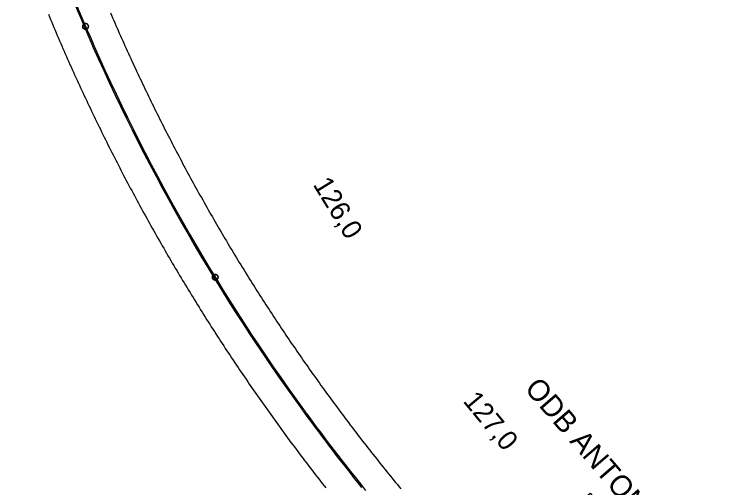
# Model space of a CAD drawing. Extents: x -670810 to -649614, y -1131928 to -1115069.
# Drawn here: x -670388 to -667816, y -1121929 to -1120256 of the extents above; entities that cross this region are included whole.
import ezdxf

# ---------------------------------------------------------------- set-up
doc = ezdxf.new("R2010")
doc.units = 0
for name, color, linetype in [('519 Var SK-4 Praporky stanic', 7, 'Continuous'), ('hranice_VRT_ZUR_Vysocina', 7, 'Continuous'), ('Situace - Osa koleje 2D', 7, 'Continuous'), ('Situace - Osa koleje tunel 2D', 7, 'Continuous'), ('Staničení - hlavní staničení + kolečka 1k', 7, 'Continuous')]:
    doc.layers.add(name, color=color, linetype=linetype)

# ---------------------------------------------------------------- blocks, each defined once
blk = doc.blocks.new('Sit10Kruh_102')
at = {"layer": 'Staničení - hlavní staničení + kolečka 1k'}
blk.add_lwpolyline([(10, 0), (10, 0.6), (9.9, 1.3), (9.8, 1.9), (9.7, 2.5), (9.5, 3.1), (9.3, 3.7), (9, 4.3), (8.8, 4.8), (8.4, 5.4), (8.1, 5.9), (7.7, 6.4), (7.3, 6.8), (6.8, 7.3), (6.4, 7.7), (5.9, 8.1), (5.4, 8.4), (4.8, 8.8), (4.3, 9), (3.7, 9.3), (3.1, 9.5), (2.5, 9.7), (1.9, 9.8), (1.3, 9.9), (0.6, 10), (0, 10), (-0.6, 10), (-1.3, 9.9), (-1.9, 9.8), (-2.5, 9.7), (-3.1, 9.5), (-3.7, 9.3), (-4.3, 9), (-4.8, 8.8), (-5.4, 8.4), (-5.9, 8.1), (-6.4, 7.7), (-6.8, 7.3), (-7.3, 6.8), (-7.7, 6.4), (-8.1, 5.9), (-8.4, 5.4), (-8.8, 4.8), (-9, 4.3), (-9.3, 3.7), (-9.5, 3.1), (-9.7, 2.5), (-9.8, 1.9), (-9.9, 1.3), (-10, 0.6), (-10, 0), (-10, -0.6), (-9.9, -1.3), (-9.8, -1.9), (-9.7, -2.5), (-9.5, -3.1), (-9.3, -3.7), (-9, -4.3), (-8.8, -4.8), (-8.4, -5.4), (-8.1, -5.9), (-7.7, -6.4), (-7.3, -6.8), (-6.8, -7.3), (-6.4, -7.7), (-5.9, -8.1), (-5.4, -8.4), (-4.8, -8.8), (-4.3, -9), (-3.7, -9.3), (-3.1, -9.5), (-2.5, -9.7), (-1.9, -9.8), (-1.3, -9.9), (-0.6, -10), (0, -10), (0.6, -10), (1.3, -9.9), (1.9, -9.8), (2.5, -9.7), (3.1, -9.5), (3.7, -9.3), (4.3, -9), (4.8, -8.8), (5.4, -8.4), (5.9, -8.1), (6.4, -7.7), (6.8, -7.3), (7.3, -6.8), (7.7, -6.4), (8.1, -5.9), (8.4, -5.4), (8.8, -4.8), (9, -4.3), (9.3, -3.7), (9.5, -3.1), (9.7, -2.5), (9.8, -1.9), (9.9, -1.3)], close=True, dxfattribs=at)
blk.add_circle((0, 0), 10, dxfattribs=at)
blk = doc.blocks.new('Sit10Kruh_103')
at = {"layer": 'Staničení - hlavní staničení + kolečka 1k'}
blk.add_lwpolyline([(10, 0), (10, 0.6), (9.9, 1.3), (9.8, 1.9), (9.7, 2.5), (9.5, 3.1), (9.3, 3.7), (9, 4.3), (8.8, 4.8), (8.4, 5.4), (8.1, 5.9), (7.7, 6.4), (7.3, 6.8), (6.8, 7.3), (6.4, 7.7), (5.9, 8.1), (5.4, 8.4), (4.8, 8.8), (4.3, 9), (3.7, 9.3), (3.1, 9.5), (2.5, 9.7), (1.9, 9.8), (1.3, 9.9), (0.6, 10), (0, 10), (-0.6, 10), (-1.3, 9.9), (-1.9, 9.8), (-2.5, 9.7), (-3.1, 9.5), (-3.7, 9.3), (-4.3, 9), (-4.8, 8.8), (-5.4, 8.4), (-5.9, 8.1), (-6.4, 7.7), (-6.8, 7.3), (-7.3, 6.8), (-7.7, 6.4), (-8.1, 5.9), (-8.4, 5.4), (-8.8, 4.8), (-9, 4.3), (-9.3, 3.7), (-9.5, 3.1), (-9.7, 2.5), (-9.8, 1.9), (-9.9, 1.3), (-10, 0.6), (-10, 0), (-10, -0.6), (-9.9, -1.3), (-9.8, -1.9), (-9.7, -2.5), (-9.5, -3.1), (-9.3, -3.7), (-9, -4.3), (-8.8, -4.8), (-8.4, -5.4), (-8.1, -5.9), (-7.7, -6.4), (-7.3, -6.8), (-6.8, -7.3), (-6.4, -7.7), (-5.9, -8.1), (-5.4, -8.4), (-4.8, -8.8), (-4.3, -9), (-3.7, -9.3), (-3.1, -9.5), (-2.5, -9.7), (-1.9, -9.8), (-1.3, -9.9), (-0.6, -10), (0, -10), (0.6, -10), (1.3, -9.9), (1.9, -9.8), (2.5, -9.7), (3.1, -9.5), (3.7, -9.3), (4.3, -9), (4.8, -8.8), (5.4, -8.4), (5.9, -8.1), (6.4, -7.7), (6.8, -7.3), (7.3, -6.8), (7.7, -6.4), (8.1, -5.9), (8.4, -5.4), (8.8, -4.8), (9, -4.3), (9.3, -3.7), (9.5, -3.1), (9.7, -2.5), (9.8, -1.9), (9.9, -1.3)], close=True, dxfattribs=at)
blk.add_circle((0, 0), 10, dxfattribs=at)
blk = doc.blocks.new('_U497')
at = {"layer": '519 Var SK-4 Praporky stanic'}
blk.add_line((-45.8, -299.9), (-45.8, 299.9), dxfattribs=at)
blk.add_lwpolyline([(-45.8, 299.9), (104.2, 299.9), (54.2, 249.9), (104.2, 199.9), (-45.8, 199.9)], close=True, dxfattribs=at)
for s, p in [('km 127,451', (-97.4, -108.5)), ('= km 0,000', (-59.2, -104))]:
    blk.add_text(s, height=30, rotation=90, dxfattribs=at).set_placement(p)
blk = doc.blocks.new('_U496')
at = {"layer": '519 Var SK-4 Praporky stanic'}
blk.add_blockref('_U497', (45.8, -87.5), dxfattribs=at)
blk.add_text('ODB ANTONÍNŮV DŮL', height=75, dxfattribs=at).set_placement((-432.7, 274.9))

msp = doc.modelspace()

# ---------------------------------------------------------------- linework, layer by layer
at = {"layer": 'hranice_VRT_ZUR_Vysocina'}
for points in [[(-670047.9, -1120249.3), (-670044, -1120258.3), (-670040.1, -1120267.4), (-670036.2, -1120276.4), (-670032.3, -1120285.5), (-670028.4, -1120294.5), (-670024.4, -1120303.5), (-670020.4, -1120312.5), (-670016.5, -1120321.6), (-670012.5, -1120330.6), (-670008.5, -1120339.6), (-670004.4, -1120348.6), (-670000.4, -1120357.6), (-669996.4, -1120366.6), (-669992.3, -1120375.6), (-669988.3, -1120384.5), (-669984.2, -1120393.5), (-669980.1, -1120402.5), (-669976, -1120411.4), (-669971.9, -1120420.4), (-669967.7, -1120429.3), (-669963.6, -1120438.3), (-669959.4, -1120447.2), (-669955.2, -1120456.2), (-669951.1, -1120465.1), (-669946.9, -1120474), (-669942.7, -1120482.9), (-669938.4, -1120491.8), (-669934.2, -1120500.7), (-669930, -1120509.6), (-669925.7, -1120518.5), (-669921.4, -1120527.4), (-669917.1, -1120536.3), (-669912.8, -1120545.1), (-669908.5, -1120554), (-669904.2, -1120562.9), (-669899.9, -1120571.7), (-669895.5, -1120580.6), (-669891.2, -1120589.4), (-669886.8, -1120598.2), (-669882.4, -1120607.1), (-669878, -1120615.9), (-669873.6, -1120624.7), (-669869.2, -1120633.5), (-669864.7, -1120642.3), (-669860.3, -1120651.1), (-669855.8, -1120659.9), (-669851.4, -1120668.7), (-669846.9, -1120677.5), (-669842.4, -1120686.2), (-669837.9, -1120695), (-669833.3, -1120703.7), (-669828.8, -1120712.5), (-669824.2, -1120721.2), (-669819.7, -1120730), (-669815.1, -1120738.7), (-669810.5, -1120747.4), (-669805.9, -1120756.2), (-669801.3, -1120764.9), (-669796.7, -1120773.6), (-669792.1, -1120782.3), (-669787.4, -1120791), (-669782.7, -1120799.6), (-669778.1, -1120808.3), (-669773.4, -1120817), (-669768.7, -1120825.7), (-669764, -1120834.3), (-669759.3, -1120843), (-669754.5, -1120851.6), (-669749.8, -1120860.3), (-669745, -1120868.9), (-669740.2, -1120877.5), (-669735.4, -1120886.1), (-669730.7, -1120894.7), (-669725.8, -1120903.3), (-669721, -1120911.9), (-669716.2, -1120920.5), (-669711.3, -1120929.1), (-669706.5, -1120937.7), (-669701.6, -1120946.3), (-669696.7, -1120954.8), (-669691.8, -1120963.4), (-669686.9, -1120971.9), (-669682, -1120980.5), (-669677.1, -1120989), (-669672.1, -1120997.5), (-669667.2, -1121006.1), (-669662.2, -1121014.6), (-669657.2, -1121023.1), (-669652.2, -1121031.6), (-669647.2, -1121040.1), (-669642.2, -1121048.6), (-669637.2, -1121057), (-669632.1, -1121065.5), (-669627.1, -1121074), (-669622, -1121082.4), (-669616.9, -1121090.9), (-669611.9, -1121099.3), (-669606.8, -1121107.7), (-669601.6, -1121116.2), (-669596.5, -1121124.6), (-669591.4, -1121133), (-669586.2, -1121141.4), (-669581.1, -1121149.8), (-669575.9, -1121158.2), (-669570.7, -1121166.6), (-669565.5, -1121175), (-669560.3, -1121183.3), (-669555.1, -1121191.7), (-669549.8, -1121200), (-669544.6, -1121208.4), (-669539.3, -1121216.7), (-669534.1, -1121225.1), (-669528.8, -1121233.4), (-669523.5, -1121241.7), (-669518.2, -1121250), (-669512.9, -1121258.3), (-669507.5, -1121266.6), (-669502.2, -1121274.9), (-669496.9, -1121283.2), (-669491.5, -1121291.4), (-669486.1, -1121299.7), (-669480.7, -1121307.9), (-669475.3, -1121316.2), (-669469.9, -1121324.4), (-669464.5, -1121332.7), (-669459.1, -1121340.9), (-669453.6, -1121349.1), (-669448.2, -1121357.3), (-669442.7, -1121365.5), (-669437.2, -1121373.7), (-669431.7, -1121381.9), (-669426.2, -1121390.1), (-669420.7, -1121398.2), (-669415.2, -1121406.4), (-669409.6, -1121414.5), (-669404.1, -1121422.7), (-669398.5, -1121430.8), (-669392.9, -1121439), (-669387.3, -1121447.1), (-669381.7, -1121455.2), (-669376.1, -1121463.3), (-669370.5, -1121471.4), (-669364.9, -1121479.5), (-669359.2, -1121487.6), (-669353.6, -1121495.6), (-669347.9, -1121503.7), (-669342.2, -1121511.8), (-669336.5, -1121519.8), (-669330.8, -1121527.8), (-669325.1, -1121535.9), (-669319.4, -1121543.9), (-669313.7, -1121551.9), (-669307.9, -1121559.9), (-669302.2, -1121567.9), (-669296.4, -1121575.9), (-669290.6, -1121583.9), (-669284.8, -1121591.9), (-669279, -1121599.8), (-669273.2, -1121607.8), (-669267.4, -1121615.7), (-669261.5, -1121623.7), (-669255.7, -1121631.6), (-669249.8, -1121639.5), (-669243.9, -1121647.5), (-669238.1, -1121655.4), (-669232.2, -1121663.3), (-669226.3, -1121671.2), (-669220.3, -1121679), (-669214.4, -1121686.9), (-669208.5, -1121694.8), (-669202.5, -1121702.7), (-669198.4, -1121708.1), (-669196.6, -1121710.5), (-669190.6, -1121718.3), (-669184.6, -1121726.2), (-669178.6, -1121734), (-669172.6, -1121741.8), (-669166.6, -1121749.6), (-669160.5, -1121757.4), (-669154.5, -1121765.2), (-669148.4, -1121773), (-669142.4, -1121780.7), (-669136.3, -1121788.5), (-669130.2, -1121796.3), (-669124.1, -1121804), (-669118, -1121811.7), (-669111.9, -1121819.5), (-669105.8, -1121827.2), (-669099.6, -1121834.9), (-669093.5, -1121842.6), (-669087.3, -1121850.3), (-669081.1, -1121858), (-669076.8, -1121863.3), (-669075, -1121865.6), (-669068.8, -1121873.3), (-669062.5, -1121881), (-669056.3, -1121888.6), (-669050.1, -1121896.3), (-669043.9, -1121903.9), (-669037.6, -1121911.5), (-669031.3, -1121919.2), (-669025.1, -1121926.8), (-669018.8, -1121934.4)], [(-670267.6, -1120255), (-670263.7, -1120264.4), (-670259.8, -1120273.8), (-670255.9, -1120283.1), (-670252, -1120292.5), (-670248, -1120301.8), (-670244.1, -1120311.2), (-670240.1, -1120320.5), (-670236.1, -1120329.9), (-670232.1, -1120339.2), (-670228.1, -1120348.5), (-670224, -1120357.8), (-670220, -1120367.1), (-670215.9, -1120376.4), (-670211.9, -1120385.7), (-670207.8, -1120395), (-670203.7, -1120404.3), (-670199.6, -1120413.6), (-670195.5, -1120422.9), (-670191.3, -1120432.1), (-670187.2, -1120441.4), (-670183, -1120450.7), (-670178.8, -1120459.9), (-670174.6, -1120469.1), (-670170.4, -1120478.4), (-670166.2, -1120487.6), (-670162, -1120496.8), (-670157.8, -1120506.1), (-670153.5, -1120515.3), (-670149.2, -1120524.5), (-670145, -1120533.7), (-670140.7, -1120542.9), (-670136.4, -1120552.1), (-670132, -1120561.3), (-670127.7, -1120570.4), (-670123.4, -1120579.6), (-670119, -1120588.8), (-670114.6, -1120597.9), (-670110.2, -1120607.1), (-670105.8, -1120616.2), (-670101.4, -1120625.4), (-670097, -1120634.5), (-670092.6, -1120643.6), (-670088.1, -1120652.8), (-670083.6, -1120661.9), (-670079.2, -1120671), (-670074.7, -1120680.1), (-670070.2, -1120689.2), (-670065.7, -1120698.3), (-670061.1, -1120707.4), (-670056.6, -1120716.4), (-670052, -1120725.5), (-670047.5, -1120734.6), (-670042.9, -1120743.6), (-670038.3, -1120752.6), (-670038.3, -1120752.7), (-670033.7, -1120761.7), (-670029.1, -1120770.8), (-670024.4, -1120779.8), (-670019.8, -1120788.8), (-670015.1, -1120797.8), (-670010.5, -1120806.8), (-670005.8, -1120815.8), (-670001.1, -1120824.8), (-669996.4, -1120833.8), (-669991.6, -1120842.8), (-669986.9, -1120851.8), (-669982.2, -1120860.8), (-669977.4, -1120869.7), (-669972.6, -1120878.7), (-669967.8, -1120887.6), (-669963, -1120896.6), (-669958.2, -1120905.5), (-669953.4, -1120914.4), (-669948.6, -1120923.4), (-669943.7, -1120932.3), (-669938.9, -1120941.2), (-669934, -1120950.1), (-669929.1, -1120959), (-669924.2, -1120967.9), (-669919.3, -1120976.8), (-669914.3, -1120985.6), (-669909.4, -1120994.5), (-669904.5, -1121003.4), (-669899.5, -1121012.2), (-669894.5, -1121021), (-669889.5, -1121029.9), (-669884.5, -1121038.7), (-669879.5, -1121047.5), (-669874.5, -1121056.4), (-669869.4, -1121065.2), (-669864.4, -1121074), (-669859.3, -1121082.8), (-669854.2, -1121091.6), (-669849.1, -1121100.3), (-669844, -1121109.1), (-669838.9, -1121117.9), (-669833.8, -1121126.6), (-669828.7, -1121135.4), (-669823.5, -1121144.1), (-669818.3, -1121152.9), (-669813.2, -1121161.6), (-669808, -1121170.3), (-669802.8, -1121179), (-669797.6, -1121187.7), (-669792.3, -1121196.4), (-669787.1, -1121205.1), (-669781.8, -1121213.8), (-669776.6, -1121222.5), (-669771.3, -1121231.2), (-669766, -1121239.8), (-669760.7, -1121248.5), (-669755.4, -1121257.1), (-669750.1, -1121265.8), (-669744.7, -1121274.4), (-669739.4, -1121283), (-669734, -1121291.6), (-669728.6, -1121300.2), (-669723.2, -1121308.8), (-669717.8, -1121317.4), (-669712.4, -1121326), (-669707, -1121334.6), (-669701.6, -1121343.2), (-669696.1, -1121351.7), (-669690.6, -1121360.3), (-669685.2, -1121368.8), (-669679.7, -1121377.4), (-669674.2, -1121385.9), (-669668.7, -1121394.4), (-669663.1, -1121402.9), (-669657.6, -1121411.4), (-669652.1, -1121419.9), (-669646.5, -1121428.4), (-669640.9, -1121436.9), (-669635.3, -1121445.4), (-669629.8, -1121453.9), (-669624.1, -1121462.3), (-669618.5, -1121470.8), (-669612.9, -1121479.2), (-669607.2, -1121487.7), (-669601.6, -1121496.1), (-669595.9, -1121504.5), (-669590.2, -1121512.9), (-669584.6, -1121521.3), (-669578.8, -1121529.7), (-669573.1, -1121538.1), (-669567.4, -1121546.5), (-669561.7, -1121554.8), (-669555.9, -1121563.2), (-669550.1, -1121571.6), (-669544.4, -1121579.9), (-669538.6, -1121588.2), (-669532.8, -1121596.6), (-669527, -1121604.9), (-669521.1, -1121613.2), (-669515.3, -1121621.5), (-669509.5, -1121629.8), (-669503.6, -1121638.1), (-669497.7, -1121646.4), (-669491.8, -1121654.6), (-669486, -1121662.9), (-669480, -1121671.2), (-669474.1, -1121679.4), (-669468.2, -1121687.6), (-669462.3, -1121695.9), (-669456.3, -1121704.1), (-669450.3, -1121712.3), (-669444.4, -1121720.5), (-669438.4, -1121728.7), (-669432.4, -1121736.9), (-669426.4, -1121745.1), (-669420.3, -1121753.2), (-669414.3, -1121761.4), (-669408.3, -1121769.5), (-669402.2, -1121777.7), (-669396.1, -1121785.8), (-669390, -1121793.9), (-669383.9, -1121802.1), (-669377.8, -1121810.2), (-669371.7, -1121818.3), (-669365.6, -1121826.4), (-669361.3, -1121832), (-669359.4, -1121834.5), (-669353.3, -1121842.5), (-669347.1, -1121850.6), (-669341, -1121858.6), (-669334.8, -1121866.7), (-669328.6, -1121874.7), (-669322.4, -1121882.7), (-669316.2, -1121890.8), (-669309.9, -1121898.8), (-669303.7, -1121906.8), (-669297.4, -1121914.8), (-669291.2, -1121922.8), (-669284.9, -1121930.7)]]:
    msp.add_lwpolyline(points, dxfattribs=at)
at = {"layer": 'Situace - Osa koleje 2D'}
msp.add_lwpolyline([(-669154.7, -1121926.1), (-669143.9, -1121939.5)], dxfattribs=at)
for radius, start, end in [(7000, 197.42407, 203.79122), (7004.7, 197.45116, 203.79126), (7004.7, 203.8935, 216.02689), (7000, 203.89354, 216.06883), (7004.7, 216.17833, 218.87879), (7000, 216.2205, 218.87815)]:
    msp.add_arc((-663705.3, -1117532.4), radius, start, end, dxfattribs=at)
at = {"layer": 'Situace - Osa koleje tunel 2D'}
for radius, start, end in [(7004.7, 203.79126, 203.8935), (7000, 203.79122, 203.89354), (7004.7, 216.02689, 216.17833), (7000, 216.06883, 216.2205)]:
    msp.add_arc((-663705.3, -1117532.4), radius, start, end, dxfattribs=at)

# ---------------------------------------------------------------- block references
at = {"layer": '519 Var SK-4 Praporky stanic', "rotation": -49.222906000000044}
msp.add_blockref('_U496', (-668509.5, -1122088.1), dxfattribs=at)
at = {"layer": 'Staničení - hlavní staničení + kolečka 1k'}
for name, p, rotation in [('Sit10Kruh_102', (-670135.9, -1120297.8), -66.730577), ('Sit10Kruh_103', (-669676.7, -1121185.2), -58.54546499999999)]:
    msp.add_blockref(name, p, dxfattribs=dict(at, rotation=rotation))

# ---------------------------------------------------------------- texts
for s, rotation, p in [('126,0', 301.4545, (-669332.3, -1120857)), ('127,0', 309.6121, (-668801.5, -1121624.4))]:
    msp.add_text(s, height=70, rotation=rotation, dxfattribs=at).set_placement(p)

doc.saveas('drawing.dxf')
